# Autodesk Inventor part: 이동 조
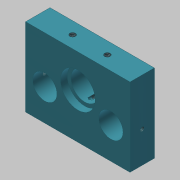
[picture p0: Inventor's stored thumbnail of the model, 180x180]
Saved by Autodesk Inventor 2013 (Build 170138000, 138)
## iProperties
Created: 2020-03
Part Number: 이동 조
Material: 알루미늄 6061
Document SubType Name: Modeling
Designer: mduedu
Density: 2.71 g/cm^3
Mass: 83.0723 g
Surface Area: 97.4821 cm^2
Volume: 30.654 cm^3
Author: mduedu
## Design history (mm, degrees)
sketch "스케치1"
  geometry: L1 (-30, 0)-(30, 0); L2 (30, 0)-(30, 48); L3 (30, 48)-(-30, 48); L4 (-30, 48)-(-30, 0); 2 further points
  constraints: 8 end point, 2 parallel, 1 coincident, 1 horizontal, 1 midpoint, 1 perpendicular
  dimensions: "d0" = 60 distance of L1.start L1.end; "d2" = 48 distance of L1.end L2.end
extrude "돌출1" new body sketch "스케치1" distance "d3" = 14; taper "d4" = 0 deg
sketch "스케치3"
  geometry: L1 (30, 0)-(-30, 0); 3 further points
  constraints: 2 end point, 1 midpoint, 1 vertical alignment
  dimensions: "d15" = 26 distance of point (0, 0) point (0, 26)
hole "구멍2" sketch "스케치3" diameter "d16" = 16; stored, may be unused: countersink angle "d20" = 90 deg, drill point angle "d22" = 118 deg; dims "d17" = 8, "d18" = 20, "d19" = 4, "d21" = 10
sketch "스케치4"
  geometry: 3 further points
  constraints: 1 horizontal alignment
  dimensions: "d23" = 18 vertical distance of point (19, 18) point (0, 0); "d24" = 19 horizontal distance of point (-19, 18) point (0, 0); "d25" = 38 distance of point (19, 18) point (-19, 18)
hole "구멍7" sketch "스케치4" at (-19, 18), (19, 18) diameter "d65" = 14; stored, may be unused: countersink angle "d69" = 90 deg, drill point angle "d71" = 118 deg; dims "d66" = 6, "d67" = 4, "d68" = 2, "d70" = 8
sketch "스케치7"
  geometry: L1 (-18, 48)-(18, 48); L2 (18, 48)-(18, 45); L3 (18, 45)-(-18, 45); L4 (-18, 45)-(-18, 48); L5 (30, 48)-(-30, 48) reference; L6 (-30, 0)-(30, 0) reference; 5 further points
  constraints: 8 end point, 2 midpoint, 2 parallel, 1 collinear, 1 horizontal, 1 perpendicular, 1 vertical alignment
  dimensions: "d50" = 3 distance of L1.end L2.end; "d52" = 36 distance of L1.start L1.end
extrude "돌출2" cut sketch "스케치7" stored distance "d53" = 10; taper "d54" = 0 deg
sketch "스케치8"
  geometry: 3 further points
  constraints: 1 horizontal alignment
  dimensions: "d55" = 7 vertical distance of point (28, 7) point (18, 14); "d56" = 10 horizontal distance of point (8, 7) point (18, 14); "d57" = 20 distance of point (28, 7) point (8, 7)
hole "구멍6" sketch "스케치8" at (8, 7), (28, 7) diameter "d58" = 3.242; stored, may be unused: countersink angle "d62" = 90 deg, drill point angle "d64" = 118 deg; dims "d59" = 6, "d60" = 4, "d61" = 2, "d63" = 8
sketch "스케치9"
  geometry: 3 further points
  constraints: 2 vertical alignment, 1 other
hole "구멍8" sketch "스케치9" at (0, 18) diameter "d75" = 2.459; stored, may be unused: countersink angle "d79" = 90 deg, drill point angle "d81" = 118 deg; dims "d76" = 5, "d77" = 4, "d78" = 2, "d80" = 7
sketch "스케치10"
  geometry: L1 (14, 0)-(14, 48) reference; L2 (14, 0)-(0, 0) reference; 2 further points
  dimensions: "d82" = 7 distance from line of point (7, 18) L1; "d83" = 18 distance from line of point (7, 18) L2
hole "구멍9" sketch "스케치10" at (7, 18) diameter "d84" = 2.459; stored, may be unused: countersink angle "d88" = 90 deg, drill point angle "d90" = 118 deg; dims "d85" = 8, "d86" = 4, "d87" = 2, "d89" = 10
node "작업 평면1"
sketch "스케치11"
  geometry: L1 (0, 14)-(0, 0) reference; L2 (36, 0)-(0, 0) reference; L3 (48, 0)-(36, 0) reference; L4 (48, 14)-(48, 0) reference; L5 (36, 14)-(48, 14) reference; L6 (36, 0)-(36, 14) reference; L7 (0, 14)-(36, 14) reference; L8 (-12, 14)-(0, 14) reference; L9 (-12, 0)-(-12, 14) reference; L10 (0, 0)-(-12, 0) reference; C1 r 1.621 at (8, 7) reference; C2 r 1.621 at (28, 7) reference; 1 further point
extrude "돌출3" cut sketch "스케치11" stored distance "d91" = 10; taper "d92" = 0 deg
node "솔리드1"
mirror "대칭1"
node "절단 모서리 투영1"
